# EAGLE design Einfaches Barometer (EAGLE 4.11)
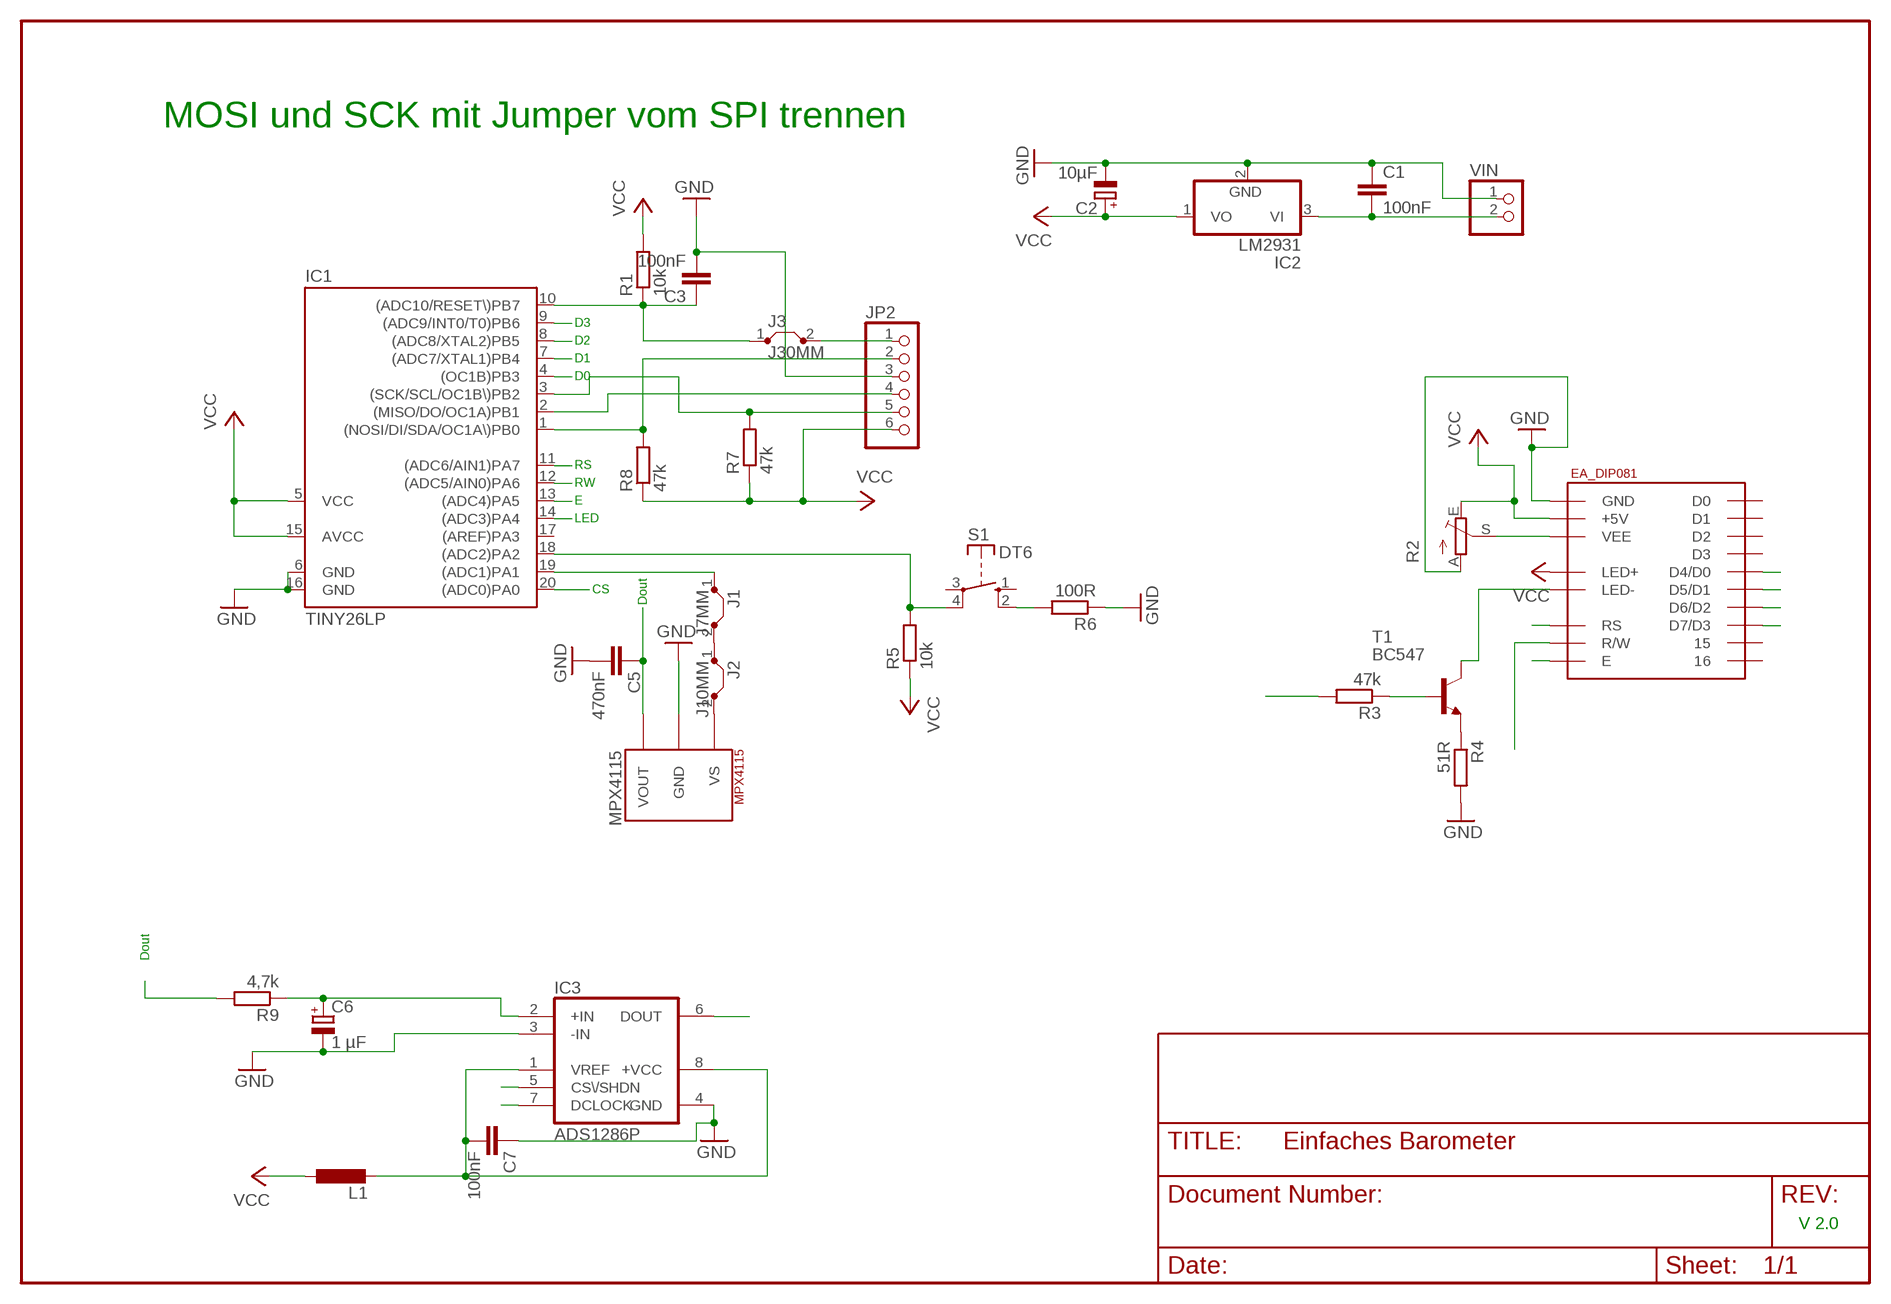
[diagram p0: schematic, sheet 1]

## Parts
C1  100nF  C-EU050-025X075  [C050-025X075]
C2  10µF  CPOL-EUE2,5-6E  [E2,5-6E]
C3  100nF  C-EU050-025X075  [C050-025X075]
C5  470nF  C-EU050-025X075  [C050-025X075]
C6  1 µF  CPOL-EUE2.5-5  [E2,5-5]
C7  100nF  C-EU050-025X075  [C050-025X075]
EA_DIP081  EA_DIP081  [DIP081]
IC1  TINY26LP  [DIL20]
IC2  LM2931  78L05Z  [TO92]
IC3  ADS1286P  [DIL08]
J1  J7MM  [07]
J2  J10MM  [10]
J3  J30MM  [30]
JP2  PINHD-1X6  [1X06]
L1  L-EU0207/12  [0207/12]
MPX4115  MPX4115_DIP  [CASE867]
R1  10k  R-EU_0207/10  [0207/10]
R2  TRIM_EU-CA6V  [CA6V]
R3  47k  R-EU_0207/10  [0207/10]
R4  51R  R-EU_0207/10  [0207/10]
R5  10k  R-EU_0207/10  [0207/10]
R6  100R  R-EU_0207/10  [0207/10]
R7  47k  R-EU_0207/10  [0207/10]
R8  47k  R-EU_0207/7  [0207/7]
R9  4,7k  R-EU_0207/10  [0207/10]
S1  DT6  [DT6]
T1  BC547  [TO92]
VIN  PINHD-1X2  [1X02]

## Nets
CS: IC1.20((ADC0)PA0) IC3.5(CS\/SHDN)
D0: EA_DIP081.11(D4/D0) IC1.4((OC1B)PB3)
D1: EA_DIP081.12(D5/D1) IC1.7((ADC7/XTAL1)PB4)
D2: EA_DIP081.13(D6/D2) IC1.8((ADC8/XTAL2)PB5)
D3: EA_DIP081.14(D7/D3) IC1.9((ADC9/INT0/T0)PB6)
DOUT: IC1.1((NOSI/DI/SDA/OC1A\)PB0) IC3.6(DOUT) JP2.2 R8.2
E: EA_DIP081.6(E) IC1.13((ADC4)PA5)
GND [Power]: C1.1 C2.- C3.2 C5.2 C6.- C7.1 EA_DIP081.1(GND) IC1.6(GND) IC1.16(GND) IC2.2(GND) IC3.3(-IN) IC3.4(GND) JP2.3 MPX4115.GND R2.A R4.2 R6.1 VIN.1
LED: IC1.14((ADC3)PA4) R3.2
N$1 [Power]: C1.2 IC2.3(VI) VIN.2
N$2: C3.1 IC1.10((ADC10/RESET\)PB7) J3.1 R1.1
N$3 [Power]: C7.2 IC3.1(VREF) IC3.8(+VCC) L1.2
N$4: C6.+ IC3.2(+IN) R9.1
N$5: IC1.2((MISO/DO/OC1A)PB1) JP2.4
N$6: J3.2 JP2.1
N$7: IC1.18((ADC2)PA2) R5.2 S1.4(P)
N$8: R6.2 S1.2(S)
N$10: IC1.19((ADC1)PA1) J1.1
N$11: J2.2 MPX4115.VS
N$12: J1.2 J2.1
N$15: EA_DIP081.3(VEE) R2.S
N$17: R3.1 T1.2(B)
N$18: R4.1 T1.1(E)
N$19: EA_DIP081.18(LED-) T1.3(C)
RS: EA_DIP081.4(RS) IC1.11((ADC6/AIN1)PA7)
RW: EA_DIP081.5(R/W) IC1.12((ADC5/AIN0)PA6)
SCK: IC1.3((SCK/SCL/OC1B\)PB2) IC3.7(DCLOCK) JP2.5 R7.2
VCC [Power]: C2.+ EA_DIP081.2(+5V) EA_DIP081.17(LED+) IC1.5(VCC) IC1.15(AVCC) IC2.1(VO) JP2.6 L1.1 R1.2 R2.E R5.1 R7.1 R8.1
VOUT: C5.1 MPX4115.VOUT R9.2
Unconnected: EA_DIP081.7(D0) EA_DIP081.8(D1) EA_DIP081.9(D2) EA_DIP081.10(D3) EA_DIP081.15 EA_DIP081.16 IC1.17((AREF)PA3) S1.1(S) S1.3(P)

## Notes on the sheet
- MOSI und SCK mit Jumper vom SPI trennen
- D3
- D2
- D1
- D0
- RS
- RW
- E
- LED
- CS
- Dout
- Dout
- V 2.0

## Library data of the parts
C1 C3 C5 C7 = rcl:C-EU: CAPACITOR, European symbol
C2 C6 = rcl:CPOL-EU: POLARIZED CAPACITOR, European symbol
EA_DIP081 = Electronic Assembly:EA_DIP081
IC1 = atmel:TINY26*: 8-bit AVR Microcontroller with 2K Bytes Flash
IC2 = linear:78*: Positive VOLTAGE REGULATOR
IC3 = burr-brown:ADS1286: 12-Bit Micro Power Sampling ADC
J1-J3 = jumper:J: Bridge
JP2 = pinhead:PINHD-1X6: PIN HEADER
L1 = rcl:L-EU: INDUCTOR, European symbol
MPX4115 = freescale:MPX4115_DIP
R1 R3-R9 = rcl:R-EU_: RESISTOR, European symbol
R2 = pot:TRIM_EU-: POTENTIOMETER
S1 = switch-misc:DT: ITT SWITCH
T1 = transistor:BC547: NPN TRANSISTOR
VIN = pinhead:PINHD-1X2: PIN HEADER

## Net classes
1 Power: width 0.381 mm

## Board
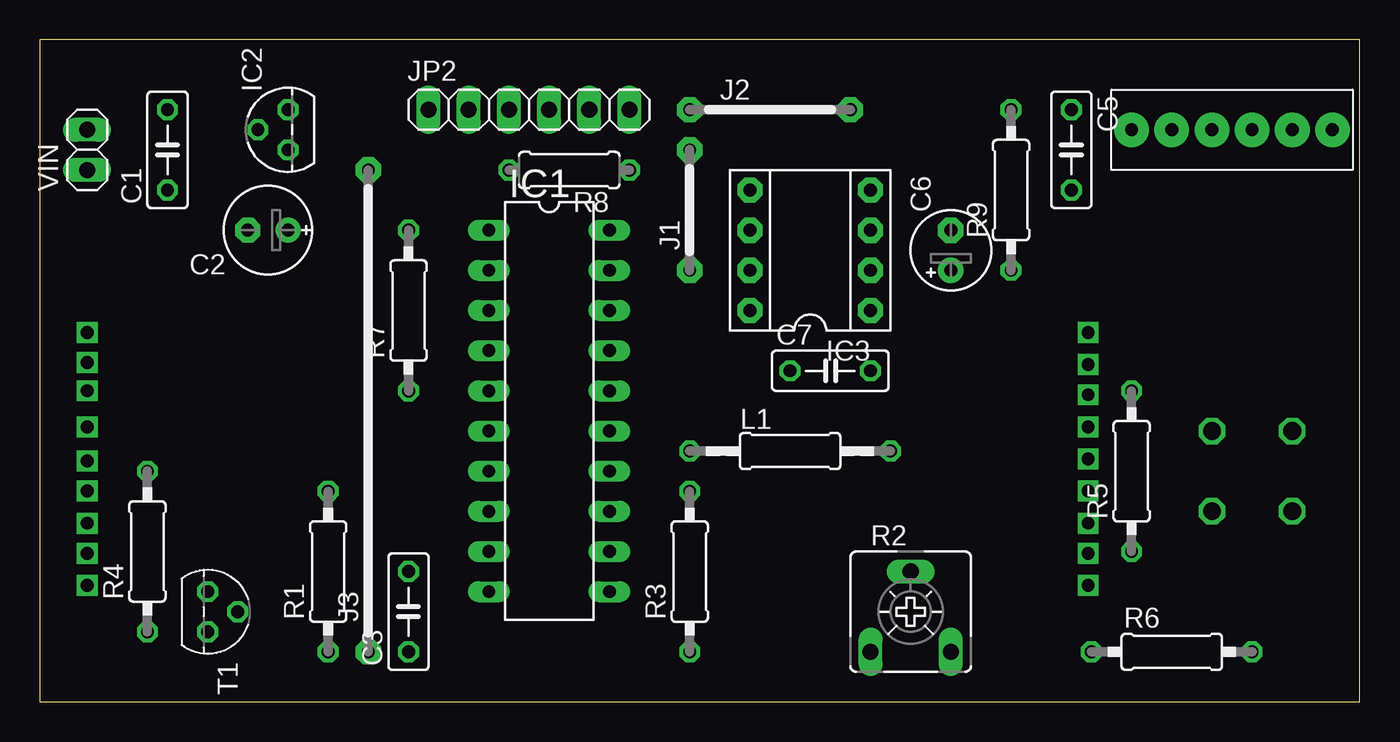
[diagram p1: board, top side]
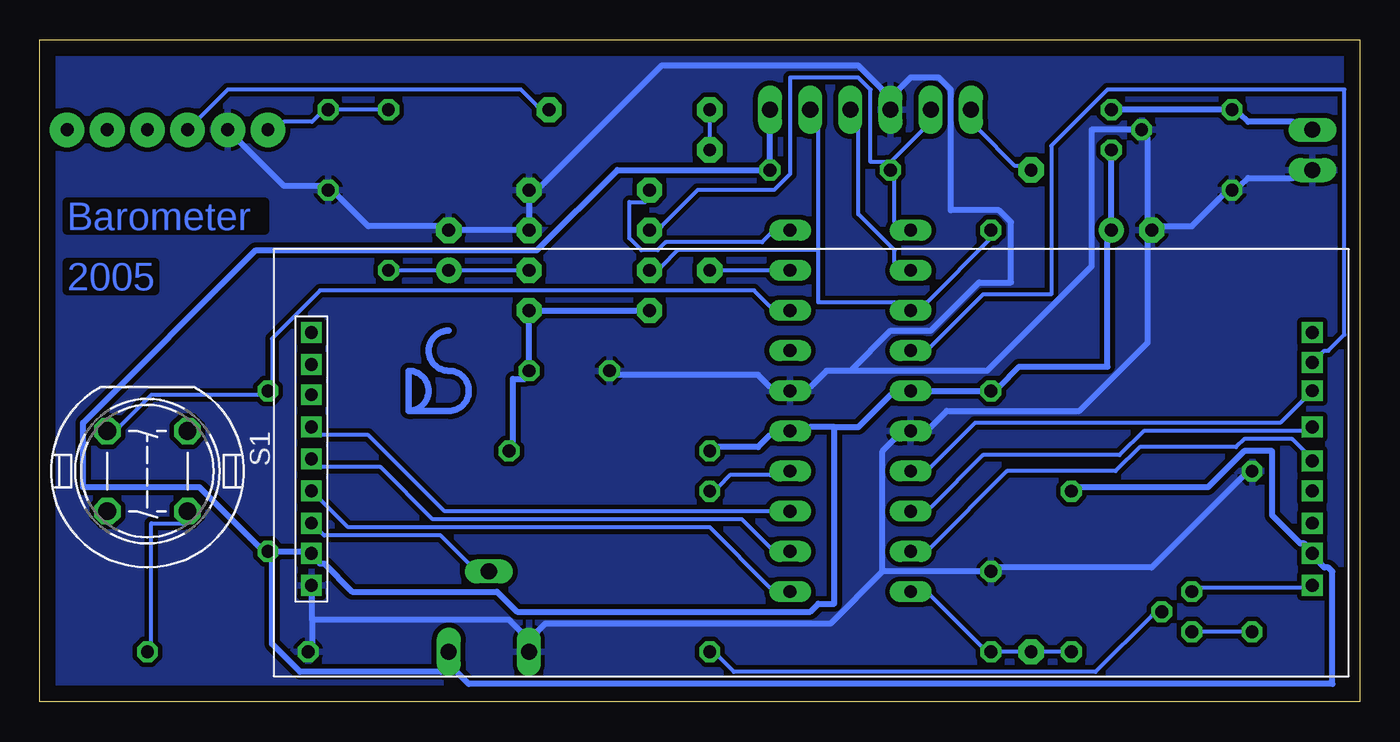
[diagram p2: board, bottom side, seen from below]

Size 83.49 x 41.9 mm. Coordinates in mm from the lower left corner, seen from the top.
Outline: 0,0 83.49,0 83.49,41.9 0,41.9 0,0
Copper layers (1*16): Top 0.035mm / dielectric 1.5mm / Bottom 0.035mm
Design rules "default": minimum track width 10mil, minimum drill 24mil, track to track 12mil, track to pad 12mil, pad to pad 12mil, via to via 12mil, smd to smd 8mil, copper to edge 40mil, drill to drill 8mil, minimum pad ring 10mil, minimum via ring 8mil, stop-mask expansion 4mil, vias tented up to drill 0mil, thermal gap 10mil

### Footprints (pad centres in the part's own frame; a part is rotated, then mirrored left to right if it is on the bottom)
C050-025X075 = drill 0.813 octagon: 1 -2.54,0; 2 2.54,0
E2,5-6E = drill 0.813 pad 1.575 round: + -1.27,0 | drill 0.813 pad 1.575 octagon: - 1.27,0
E2,5-5 = drill 0.813 pad 1.6 round: + -1.27,0 | drill 0.813 pad 1.6 octagon: - 1.27,0
DIP081 = drill 0.813 square: 1 -29,-8.5; 2 -29,-6.468; 3 -29,-4.563; 4 -29,-2.531; 5 -29,-0.499; 6 -29,1.533; 7 -29,3.565; 8 -29,5.47; 9 -29,7.502; 10 34.278,7.502; 11 34.278,5.597; 12 34.278,3.819; 13 34.278,1.533; 14 34.278,-0.626; 15 34.278,-2.531; 16 34.278,-4.563; 17 34.278,-6.468; 18 34.278,-8.5
DIL20 = drill 0.813 long: 1 -11.43,-3.81; 2 -8.89,-3.81; 3 -6.35,-3.81; 4 -3.81,-3.81; 5 -1.27,-3.81; 6 1.27,-3.81; 7 3.81,-3.81; 8 6.35,-3.81; 9 8.89,-3.81; 10 11.43,-3.81; 11 11.43,3.81; 12 8.89,3.81; 13 6.35,3.81; 14 3.81,3.81; 15 1.27,3.81; 16 -1.27,3.81; 17 -3.81,3.81; 18 -6.35,3.81; 19 -8.89,3.81; 20 -11.43,3.81
TO92 = drill 0.813 octagon: 1 -1.27,0; 2 0,1.905; 3 1.27,0
DIL08 = drill 0.813 pad 1.6 octagon: 1 -3.81,-3.81; 2 -1.27,-3.81; 3 1.27,-3.81; 4 3.81,-3.81; 5 3.81,3.81; 6 1.27,3.81; 7 -1.27,3.81; 8 -3.81,3.81
07 = drill 0.813 pad 1.6 octagon: 1 -3.81,0; 2 3.81,0
10 = drill 0.813 pad 1.6 octagon: 1 -5.08,0; 2 5.08,0
30 = drill 0.813 pad 1.6 octagon: 1 -15.24,0; 2 15.24,0
1X06 = drill 1.016 long: 1 -6.35,0; 2 -3.81,0; 3 -1.27,0; 4 1.27,0; 5 3.81,0; 6 6.35,0
0207/12 = drill 0.813 octagon: 1 -6.35,0; 2 6.35,0
CASE867 = drill 0.813 pad 2.184 round: 4 1.27,0; 5 3.81,0; 6 6.35,0; GND -3.81,0; VOUT -6.35,0; VS -1.27,0
0207/10 = drill 0.813 octagon: 1 -5.08,0; 2 5.08,0
CA6V = drill 1.016 long: A -2.54,-2.54; E 2.54,-2.54; S 0,2.54
0207/7 = drill 0.813 octagon: 1 -3.81,0; 2 3.81,0
DT6 = drill 1.118 octagon: 1 -2.54,2.54; 2 2.54,2.54; 3 2.54,-2.54; 4 -2.54,-2.54
TO92' = drill 0.813 octagon: 1 1.27,0; 2 0,1.905; 3 -1.27,0
1X02 = drill 1.016 long: 1 -1.27,0; 2 1.27,0

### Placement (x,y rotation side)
C1  8.09,34.92 90 top
C2  14.44,29.84 180 top
C3  23.33,5.71 90 top
C5  65.24,34.92 270 top
C6  57.62,28.57 90 top
C7  50,20.95 0 top
EA_DIP081  37.3,15.87 0 bottom
IC1  32.22,18.41 270 top
IC2  15.71,36.19 90 top
IC3  48.73,28.57 90 top
J1  41.11,31.11 90 top
J2  46.19,37.46 0 top
J3  20.79,18.41 90 top
JP2  30.95,37.46 0 top
L1  47.46,15.87 0 top
MPX4115  75.4,36.19 0 top
R1  18.25,8.25 90 top
R2  55.08,5.71 0 top
R3  41.11,8.25 90 top
R4  6.82,9.52 90 top
R5  69.05,14.6 90 top
R6  71.59,3.17 0 top
R7  23.33,24.76 90 top
R8  33.49,33.65 180 top
R9  61.43,32.38 90 top
S1  76.67,14.6 270 bottom
T1  BC547  [TO92']  10.63,5.71 270 top
VIN  3.01,34.92 90 top

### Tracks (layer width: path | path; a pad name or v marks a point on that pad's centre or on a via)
CS
  Bottom 0.254: IC1.20 37.3,29.59 37.81,29.08 43.9,29.08 44.41,28.57 45.43,28.57 46.19,29.33 46.19,31.62 45.17,31.62 IC3.5
D0
  Bottom 0.254: EA_DIP081.11 2.5,21.97 2.25,22.22 1.99,22.22 0.98,23.24 0.98,38.73 15.96,38.73 19.52,35.17 19.52,25.78 23.84,25.78 27.14,22.47 IC1.4
D1
  Bottom 0.254: EA_DIP081.12 3.52,19.17 5.04,17.65 24.35,17.65 27.14,14.85 IC1.7
D2
  Bottom 0.254: IC1.8 27.14,12.31 23.84,15.62 15.2,15.62 13.68,17.14 3.52,17.14 EA_DIP081.13
D3
  Bottom 0.254: EA_DIP081.14 3.52,15.87 4.28,16.63 7.33,16.63 7.84,16.12 13.93,16.12 15.46,14.6 22.31,14.6 27.14,9.77 IC1.9
DOUT
  Bottom 0.254: IC1.1 29.43,30.35 29.43,33.14 R8.2 | JP2.2 27.65,36.19 29.68,34.16 R8.2 | IC3.6 44.16,30.09 41.87,32.38 37.05,32.38 36.03,33.4 36.03,39.49 31.71,39.49 30.95,38.73 30.95,34.16 29.93,34.16 R8.2
E
  Bottom 0.254: IC1.13 57.87,12.06 62.7,16.89 65.75,16.89 EA_DIP081.6
GND
  Bottom 0.381: 66.26,5.2 66.26,3.68 R6.1 | 66.26,5.2 66.26,6.73 EA_DIP081.1 | 66.26,5.2 53.81,5.2 53.05,4.44 R2.A 52.03,4.44 51.52,4.95 33.49,4.95 30.19,8.25 | R4.2 7.33,14.35 13.17,8.5 22.82,8.5 C3.2 30.19,8.25 | 30.19,8.25 30.19,15.87 29.43,16.63 IC1.6 27.14,17.39 26.12,18.41 17.74,18.41 13.42,22.73 13.42,29.08 C2.- | MPX4115.GND 68.03,32.63 65.75,32.63 C5.2 64.73,32.13 62.7,30.09 58.38,30.09 C6.- IC3.3 IC3.4 51.78,32.63 44.16,40.25 31.71,40.25 30.19,38.73 JP2.3 29.17,38.73 28.41,39.49 26.63,39.49 25.87,38.73 25.87,31.11 22.82,31.11 22.06,30.35 22.06,26.54 24.09,26.54 27.14,23.49 29.68,23.49 32.22,20.95 | C7.1 46.95,20.7 38.06,20.7 37.3,19.93 IC1.16 34.76,19.93 33.74,20.95 32.22,20.95 | VIN.1 4.28,33.14 7.07,33.14 7.58,32.63 C1.1 8.6,32.13 10.63,30.09 12.41,30.09 C2.- | C2.- 13.42,30.6 13.42,35.68 IC2.2 16.98,36.19 16.98,27.55 23.58,20.95 32.22,20.95
  pour Bottom: 0.47,41.27 83.02,41.27 83.02,0.63 0.47,0.63
LED
  Bottom 0.254: R3.2 40.6,13.58 39.84,14.35 37.3,14.35 IC1.14
N$1
  Bottom 0.381: VIN.2 4.28,36.7 7.07,36.7 7.58,37.21 C1.2 IC2.3
N$2
  Bottom 0.254: R1.1 J3.1 C3.1 23.84,3.42 27.14,6.73 IC1.10
N$3
  Bottom 0.381: L1.2 53.56,16.38 53.56,20.44 52.79,20.44 C7.2 IC3.1 IC3.8
N$4
  Bottom 0.254: R9.1 C6.+ IC3.2
N$5
  Bottom 0.254: IC1.2 29.43,27.81 29.43,28.57 31.71,30.86 31.71,36.19 JP2.4
N$6
  Bottom 0.254: JP2.1 24.09,36.19 21.81,33.9 21.55,33.9 J3.2
N$7
  Bottom 0.254: IC1.18 37.3,25.01 38.32,26.03 65.75,26.03 68.8,22.98 68.8,20.19 R5.2 69.56,19.43 76.42,19.43 78.45,17.39 S1.4
N$8
  Bottom 0.254: R6.2 76.42,3.68 76.42,11.3 74.38,11.3 S1.2
N$9
  Bottom 0.406: 57.62,23.49 arc-180 57.62,20.95 arc180 57.62,18.41 60.16,18.41 | 60.16,18.41 arc-180 60.16,20.95 60.16,18.41
N$10
  Bottom 0.254: IC1.19 J1.1
N$11
  Bottom 0.254: J2.2 52.03,37.71 53.05,38.73 71.59,38.73 MPX4115.VS
N$12
  Bottom 0.254: J1.2 J2.1
N$13
  pour Bottom: 83.02,0.63 0.47,0.63 0.47,41.27 83.02,41.27
N$15
  Bottom 0.254: EA_DIP081.3 65.75,10.79 65.49,10.54 58.13,10.54 56.35,8.76 R2.S
N$17
  Bottom 0.254: T1.2 13.17,5.46 16.73,1.9 39.59,1.9 40.6,2.92 R3.1
N$18
  Bottom 0.254: R4.1 T1.1
N$19
  Bottom 0.254: EA_DIP081.18 3.52,7.23 10.12,7.23 T1.3
RS
  Bottom 0.254: IC1.11 37.3,7.23 41.11,11.04 63.97,11.04 65.75,12.82 EA_DIP081.4
RW
  Bottom 0.254: IC1.12 37.3,9.77 39.08,11.55 58.64,11.55 61.94,14.85 65.75,14.85 EA_DIP081.5
SCK
  Bottom 0.254: R7.2 23.33,29.33 27.39,25.27 IC1.3 29.43,25.27 34.25,25.27 34.25,28.57 | 34.25,28.57 34.25,36.19 JP2.5 | 34.25,28.57 43.14,28.57 44.16,27.55 IC3.7
VCC
  Bottom 0.381: IC2.1 C2.+ 15.96,29.08 15.96,21.2 21.55,21.2 22.82,19.93 R7.1 IC1.5 29.68,19.43 31.71,17.39 33.24,17.39 | L1.1 40.6,16.12 38.06,16.12 37.3,16.89 IC1.15 34.76,17.39 33.24,17.39 | R1.2 17.74,13.58 9.61,13.58 7.33,15.87 5.55,15.87 5.55,11.81 3.77,10.03 3.52,10.03 EA_DIP081.17 2.5,8.76 2.25,8.5 1.99,8.5 1.74,8.25 1.74,1.14 56.35,1.14 57.11,1.9 R2.E 58.13,1.9 67.02,1.9 68.8,3.68 68.8,9.01 R5.1 | JP2.6 R8.1 46.95,33.65 52.03,28.57 69.81,28.57 80.73,17.65 80.73,13.58 73.37,13.58 69.56,9.77 R5.1 | R5.1 66.76,9.52 EA_DIP081.2 65.75,8.76 65.49,8.76 63.72,6.98 54.57,6.98 53.3,5.71 34.76,5.71 34.25,6.22 33.24,6.22 33.24,17.39
VOUT
  Bottom 0.254: R9.2 C5.1 65.75,37.21 66.26,36.7 68.03,36.7 MPX4115.VOUT

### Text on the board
Bottom: Barometer | 2005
